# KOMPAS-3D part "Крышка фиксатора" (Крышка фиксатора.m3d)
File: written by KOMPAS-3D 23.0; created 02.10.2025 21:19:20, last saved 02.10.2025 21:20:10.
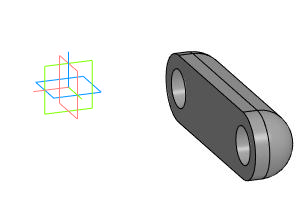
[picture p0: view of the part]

Document properties: Автор: Inspektor_Kot; Полное имя файла: I:\Autodesk Inventor Projects\ИМ-ИТ ЦД\Вариант 9\Крышка фиксатора.m3d

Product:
- Part/product: Крышка фиксатора
    Масса: 4.772413

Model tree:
1. Эскиз:1  (with: Элемент выдавливания:1, Скругление:1)
2. Элемент выдавливания:1
     Расстояние 1 = 50
3. Эскиз:3  (with: Элемент выдавливания:1)
4. Элемент выдавливания:2  (with: Элемент выдавливания:1)
     Расстояние 1 = -20
5. Скругление:1  (with: Элемент выдавливания:1)
     Радиус = 35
